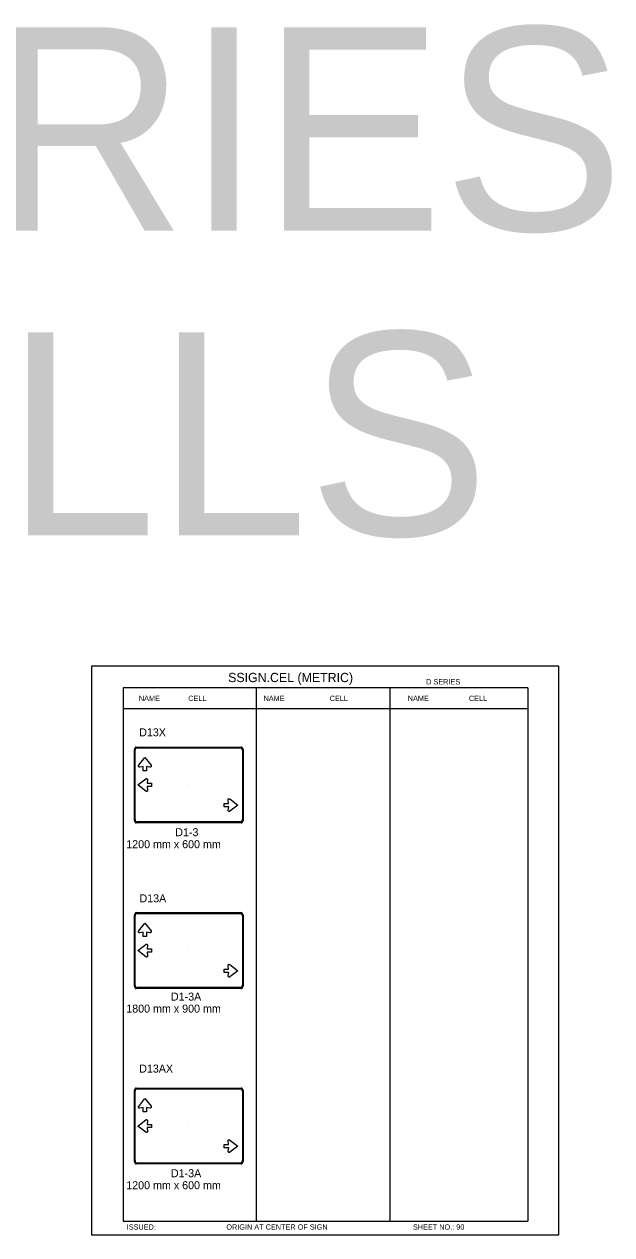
# Model space of a CAD drawing. Extents: x -12 to 6962, y -3756 to 679.
# Drawn here: x 4366.4 to 4586.7, y 225.3 to 679.1 of the extents above; entities that cross this region are included whole.
import ezdxf

# ---------------------------------------------------------------- set-up
doc = ezdxf.new("R2010")
doc.units = 0
for name, color, linetype in [('Level 1', 7, 'Continuous'), ('Level 2', 7, 'Continuous'), ('Level 3', 7, 'Continuous'), ('Level 61', 7, 'Continuous')]:
    doc.layers.add(name, color=color, linetype=linetype)

msp = doc.modelspace()

# ---------------------------------------------------------------- linework, layer by layer
at = {"layer": 'Level 1'}
for p, q in [((4555.25, 430.35), (4403.5, 430.35)), ((4403.5, 430.35), (4403.5, 230.35)), ((4453.42, 430.35), (4453.42, 230.35)), ((4503.49, 430.35), (4503.49, 230.35)), ((4555.25, 430.35), (4555.25, 230.35)), ((4555.25, 422.43), (4403.5, 422.43)), ((4407.77, 380.63), (4407.77, 407.18)), ((4408.02, 380.91), (4408.02, 406.9)), ((4408.45, 408.13), (4447.8, 408.13)), ((4408.65, 407.78), (4447.6, 407.78)), ((4448.23, 406.9), (4448.23, 380.91)), ((4448.48, 407.18), (4448.48, 380.63)), ((4428.12, 393.9), (4428.12, 393.9)), ((4447.8, 379.68), (4408.45, 379.68)), ((4447.6, 380.03), (4408.65, 380.03)), ((4407.77, 318.55), (4407.77, 345.1)), ((4408.45, 346.05), (4447.8, 346.05)), ((4408.65, 345.7), (4447.6, 345.7)), ((4448.48, 345.1), (4448.48, 318.55)), ((4408.02, 318.83), (4408.02, 344.82)), ((4448.23, 344.82), (4448.23, 318.83)), ((4428.12, 331.83), (4428.12, 331.83)), ((4447.6, 317.95), (4408.65, 317.95)), ((4447.8, 317.6), (4408.45, 317.6)), ((4407.77, 252.81), (4407.77, 279.36)), ((4408.02, 253.09), (4408.02, 279.08)), ((4408.45, 280.31), (4447.8, 280.31)), ((4408.65, 279.95), (4447.6, 279.95)), ((4448.23, 279.08), (4448.23, 253.09)), ((4448.48, 279.36), (4448.48, 252.81)), ((4428.12, 266.08), (4428.12, 266.08)), ((4447.8, 251.86), (4408.45, 251.86)), ((4447.6, 252.21), (4408.65, 252.21)), ((4403.5, 230.35), (4555.25, 230.35))]:
    msp.add_line(p, q, dxfattribs=at)
for points in [[(4411.68, 404.21), (4413.97, 401.3), (4414.03, 401.22), (4414.06, 401.1), (4414.07, 400.97), (4414.03, 400.87), (4413.98, 400.76), (4413.91, 400.7), (4413.8, 400.63), (4413.78, 400.62), (4413.69, 400.59), (4413.6, 400.59), (4413.58, 400.59), (4412.3, 400.81), (4412.3, 399.16), (4411.08, 399.16), (4411.08, 400.8), (4409.78, 400.57), (4409.77, 400.57), (4409.7, 400.56), (4409.59, 400.59), (4409.49, 400.6), (4409.41, 400.67), (4409.34, 400.74), (4409.31, 400.81), (4409.28, 400.89), (4409.26, 400.96), (4409.27, 401.06), (4409.3, 401.16), (4409.36, 401.27), (4411.68, 404.21)], [(4409.06, 393.91), (4411.97, 396.19), (4412.05, 396.25), (4412.17, 396.28), (4412.3, 396.29), (4412.41, 396.25), (4412.51, 396.2), (4412.58, 396.13), (4412.64, 396.03), (4412.65, 396.01), (4412.68, 395.91), (4412.68, 395.83), (4412.69, 395.81), (4412.46, 394.53), (4414.11, 394.53), (4414.11, 393.3), (4412.48, 393.3), (4412.7, 392), (4412.7, 391.99), (4412.71, 391.92), (4412.68, 391.81), (4412.67, 391.71), (4412.61, 391.63), (4412.53, 391.56), (4412.46, 391.53), (4412.38, 391.5), (4412.31, 391.48), (4412.21, 391.49), (4412.12, 391.52), (4412, 391.59), (4409.06, 393.91)], [(4446.48, 386.33), (4443.57, 384.05), (4443.49, 383.99), (4443.37, 383.95), (4443.24, 383.95), (4443.14, 383.99), (4443.03, 384.04), (4442.97, 384.1), (4442.9, 384.21), (4442.89, 384.23), (4442.86, 384.32), (4442.86, 384.41), (4442.86, 384.43), (4443.08, 385.71), (4441.43, 385.71), (4441.43, 386.94), (4443.07, 386.94), (4442.84, 388.24), (4442.84, 388.24), (4442.83, 388.31), (4442.86, 388.42), (4442.87, 388.53), (4442.94, 388.6), (4443.01, 388.68), (4443.08, 388.7), (4443.16, 388.73), (4443.23, 388.76), (4443.33, 388.74), (4443.43, 388.71), (4443.54, 388.65), (4446.48, 386.33)], [(4411.68, 342.14), (4413.97, 339.23), (4414.03, 339.15), (4414.06, 339.02), (4414.07, 338.9), (4414.03, 338.79), (4413.98, 338.69), (4413.91, 338.62), (4413.8, 338.55), (4413.78, 338.54), (4413.69, 338.51), (4413.6, 338.52), (4413.58, 338.51), (4412.3, 338.74), (4412.3, 337.08), (4411.08, 337.08), (4411.08, 338.72), (4409.78, 338.49), (4409.77, 338.5), (4409.7, 338.49), (4409.59, 338.51), (4409.49, 338.52), (4409.41, 338.59), (4409.34, 338.67), (4409.31, 338.73), (4409.28, 338.81), (4409.26, 338.89), (4409.27, 338.99), (4409.3, 339.08), (4409.36, 339.2), (4411.68, 342.14)], [(4409.06, 331.83), (4411.97, 334.12), (4412.05, 334.17), (4412.17, 334.21), (4412.3, 334.21), (4412.41, 334.18), (4412.51, 334.12), (4412.58, 334.06), (4412.64, 333.95), (4412.65, 333.93), (4412.68, 333.84), (4412.68, 333.75), (4412.69, 333.73), (4412.46, 332.45), (4414.11, 332.45), (4414.11, 331.22), (4412.48, 331.22), (4412.7, 329.92), (4412.7, 329.92), (4412.71, 329.85), (4412.68, 329.74), (4412.67, 329.63), (4412.61, 329.56), (4412.53, 329.48), (4412.46, 329.46), (4412.38, 329.43), (4412.31, 329.4), (4412.21, 329.42), (4412.12, 329.45), (4412, 329.51), (4409.06, 331.83)], [(4446.48, 324.25), (4443.57, 321.97), (4443.49, 321.91), (4443.37, 321.88), (4443.24, 321.87), (4443.14, 321.91), (4443.03, 321.96), (4442.97, 322.03), (4442.9, 322.13), (4442.89, 322.15), (4442.86, 322.25), (4442.86, 322.33), (4442.86, 322.35), (4443.08, 323.63), (4441.43, 323.63), (4441.43, 324.86), (4443.07, 324.86), (4442.84, 326.16), (4442.84, 326.17), (4442.83, 326.24), (4442.86, 326.35), (4442.87, 326.45), (4442.94, 326.53), (4443.01, 326.6), (4443.08, 326.63), (4443.16, 326.66), (4443.23, 326.68), (4443.33, 326.67), (4443.43, 326.64), (4443.54, 326.57), (4446.48, 324.25)], [(4411.68, 276.39), (4413.97, 273.48), (4414.03, 273.4), (4414.06, 273.28), (4414.07, 273.15), (4414.03, 273.04), (4413.98, 272.94), (4413.91, 272.88), (4413.8, 272.81), (4413.78, 272.8), (4413.69, 272.77), (4413.6, 272.77), (4413.58, 272.76), (4412.3, 272.99), (4412.3, 271.34), (4411.08, 271.34), (4411.08, 272.98), (4409.78, 272.75), (4409.77, 272.75), (4409.7, 272.74), (4409.59, 272.77), (4409.49, 272.78), (4409.41, 272.84), (4409.34, 272.92), (4409.31, 272.99), (4409.28, 273.07), (4409.26, 273.14), (4409.27, 273.24), (4409.3, 273.34), (4409.36, 273.45), (4411.68, 276.39)], [(4409.06, 266.08), (4411.97, 268.37), (4412.05, 268.43), (4412.17, 268.46), (4412.3, 268.47), (4412.41, 268.43), (4412.51, 268.38), (4412.58, 268.31), (4412.64, 268.21), (4412.65, 268.18), (4412.68, 268.09), (4412.68, 268.01), (4412.69, 267.98), (4412.46, 266.7), (4414.11, 266.7), (4414.11, 265.48), (4412.48, 265.48), (4412.7, 264.18), (4412.7, 264.17), (4412.71, 264.1), (4412.68, 263.99), (4412.67, 263.89), (4412.61, 263.81), (4412.53, 263.74), (4412.46, 263.71), (4412.38, 263.68), (4412.31, 263.66), (4412.21, 263.67), (4412.12, 263.7), (4412, 263.76), (4409.06, 266.08)], [(4446.48, 258.51), (4443.57, 256.22), (4443.49, 256.16), (4443.37, 256.13), (4443.24, 256.13), (4443.14, 256.16), (4443.03, 256.22), (4442.97, 256.28), (4442.9, 256.39), (4442.89, 256.41), (4442.86, 256.5), (4442.86, 256.59), (4442.86, 256.61), (4443.08, 257.89), (4441.43, 257.89), (4441.43, 259.12), (4443.07, 259.12), (4442.84, 260.42), (4442.84, 260.42), (4442.83, 260.49), (4442.86, 260.6), (4442.87, 260.7), (4442.94, 260.78), (4443.01, 260.86), (4443.08, 260.88), (4443.16, 260.91), (4443.23, 260.93), (4443.33, 260.92), (4443.43, 260.89), (4443.54, 260.83), (4446.48, 258.51)]]:
    msp.add_lwpolyline(points, dxfattribs=at)
for centre, major_axis, start_param, end_param in [((4408.45, 407.18), (0, -0.948), 3.141593, 4.712389), ((4408.65, 406.9), (0, -0.877), 3.141593, 4.712389), ((4447.6, 406.9), (0, 0.877), 4.712389, 6.283185), ((4447.8, 407.18), (0, 0.948), 4.712389, 6.283185), ((4408.45, 380.63), (0, -0.948), 4.712389, 6.283185), ((4408.65, 380.91), (0, -0.877), 4.712389, 6.283185), ((4447.6, 380.91), (0, 0.877), 3.141593, 4.712389), ((4447.8, 380.63), (0, 0.948), 3.141593, 4.712389), ((4408.45, 345.1), (0, -0.948), 3.141593, 4.712389), ((4408.65, 344.82), (0, -0.877), 3.141593, 4.712389), ((4447.6, 344.82), (0, 0.877), 4.712389, 6.283185), ((4447.8, 345.1), (0, 0.948), 4.712389, 6.283185), ((4408.45, 318.55), (0, -0.948), 4.712389, 6.283185), ((4408.65, 318.83), (0, -0.877), 4.712389, 6.283185), ((4447.6, 318.83), (0, 0.877), 3.141593, 4.712389), ((4447.8, 318.55), (0, 0.948), 3.141593, 4.712389), ((4408.45, 279.36), (0, -0.948), 3.141593, 4.712389), ((4408.65, 279.08), (0, -0.877), 3.141593, 4.712389), ((4447.6, 279.08), (0, 0.877), 4.712389, 6.283185), ((4447.8, 279.36), (0, 0.948), 4.712389, 6.283185), ((4408.45, 252.81), (0, -0.948), 4.712389, 6.283185), ((4408.65, 253.09), (0, -0.877), 4.712389, 6.283185), ((4447.6, 253.09), (0, 0.877), 3.141593, 4.712389), ((4447.8, 252.81), (0, 0.948), 3.141593, 4.712389)]:
    msp.add_ellipse(centre, major_axis=major_axis, ratio=0.715449, start_param=start_param, end_param=end_param, dxfattribs=at)
at = {"layer": 'Level 61'}
msp.add_lwpolyline([(4391.62, 225.31), (4566.88, 225.31), (4566.88, 438.4), (4391.62, 438.4)], close=True, dxfattribs=at)

# ---------------------------------------------------------------- texts
at = {"layer": 'Level 2'}
for s, p in [('D13X', (4409.52, 412.13)), ('D13A', (4409.63, 349.92)), ('D13AX', (4409.52, 286.1))]:
    msp.add_text(s, height=3, dxfattribs=at).set_placement(p)
at = {"layer": 'Level 3'}
for s, height, p in [('D-SERIES', 76.194, (4110.17, 601.72)), ('CELLS', 76.194, (4217.9, 487.43)), ('SSIGN.CEL (METRIC)', 3.4642, (4442.88, 432.46)), ('D SERIES', 1.979, (4517.13, 431.59)), ('NAME', 1.98, (4409.4, 425.39)), ('CELL', 1.98, (4427.93, 425.39)), ('NAME', 1.98, (4456.14, 425.39)), ('CELL', 1.98, (4480.95, 425.39)), ('NAME', 1.98, (4510.23, 425.39)), ('CELL', 1.98, (4533.15, 425.39)), ('D1-3', 3, (4423.06, 374.7)), ('1200 mm x 600 mm', 3, (4404.68, 370.2)), ('D1-3A', 3, (4421.43, 313.08)), ('1800 mm x 900 mm', 3, (4404.68, 308.58)), ('D1-3A', 3, (4421.43, 246.88)), ('1200 mm x 600 mm', 3, (4404.68, 242.38)), ('ISSUED:', 1.98, (4404.84, 227.23)), ('ORIGIN AT CENTER OF SIGN', 1.9795, (4442.22, 227.23)), ('SHEET NO.: 90', 1.9795, (4512.17, 227.23))]:
    msp.add_text(s, height=height, dxfattribs=at).set_placement(p)

doc.saveas('drawing.dxf')
